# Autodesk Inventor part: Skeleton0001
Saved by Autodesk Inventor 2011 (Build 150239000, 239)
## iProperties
Created: 2020-11
Part Number: Skeleton0001
Document SubType Name: Modeling
Designer: PC
Density: 1 g/cm^3
_SkeletonDoc: Frame Skeleton File
_Version: 15.0.0
Author: PC
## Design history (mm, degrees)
sketch "Reference Skeleton"
